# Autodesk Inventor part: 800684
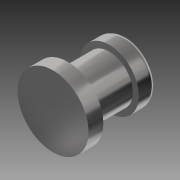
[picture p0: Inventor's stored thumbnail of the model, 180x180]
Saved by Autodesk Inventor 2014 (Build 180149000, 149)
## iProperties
Created: 2007-10
Part Number: 800684
Document SubType Name: Modeling
Designer: AL
Density: 8.08 g/cm^3
Mass: 6.97935 g
Surface Area: 6.33239 cm^2
Volume: 0.86378 cm^3
Material: Stainless Steel
Description: PIVOT PIN
Appearance: Steel - Polished
Component Category: Fasteners
Author: AL
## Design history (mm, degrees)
sketch "Sketch1"
  geometry: L1 (-1.2, 0)-(7.2, 0) reference; L2 (0, -8.541)-(0, 9.249) reference; L3 (0, -6)-(6, -6); L4 (6, -6)-(6, -3.5); L5 (6, -3.5)-(4, -3.5); L6 (4, -3.5)-(4, 3.5); L7 (4, 3.5)-(5, 3.5); L8 (5, 3.5)-(5, 5.5); L9 (4, 6.5)-(0, 6.5); A1 r 1 centre (4, 5.5) between (5, 5.5) and (4, 6.5); 2 further points
  constraints: 14 end point, 5 perpendicular, 3 point on line, 2 parallel, 2 point on circle, 2 tangent, 1 centre point, 1 midpoint
  dimensions: "d1" = 10 diameter of L8 L2; "d2" = 8 diameter of L6 L2; "d3" = 12 diameter of L4 L2; "d4" = 7 distance between parallel lines of L7 L5; "d5" = 3 distance between parallel lines of L9 L7; "d6" = 2.5 distance between parallel lines of L3 L5; "d7" = 1 radius of A1
revolve "Revolution1" sketch "Sketch1" stored, may be unused: angle "d8" = 90 deg
body "Solid1"
